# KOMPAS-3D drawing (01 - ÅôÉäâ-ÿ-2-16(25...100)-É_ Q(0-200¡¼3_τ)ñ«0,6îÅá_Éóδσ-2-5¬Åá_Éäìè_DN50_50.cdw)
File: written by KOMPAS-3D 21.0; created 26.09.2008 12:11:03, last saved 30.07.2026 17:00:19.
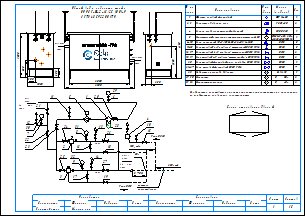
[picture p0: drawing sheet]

Sheets 1-2: A3, landscape

Document properties: Наименование: Макро:21; Автор: RaskoAdmin; Форматы листов документа: 2xA3; Полное имя файла: \\UR38nt01\Departments\КТО\КБ ПУРДГ\Заявки\Прайс-лист на типовые шкафы ГРПШ\ПУРДГ_стандарт_30_04_2026\ПУРДГ с РДНК\ПУРДГ-Ш-2-16(25...100)-Р_ Q(0-200нм3_ч)до0,6МПа_Рвых-2-5кПа_РДНК_DN50_50.cdw

Title block, sheet 1: Наименование: Пункт учета газа / ПУГ-Ш-400-Р / ЛГТИ.485922.001ТУ; designation: ЛГТИ.03.4411141; sheet number: 1; Количество листов документа: 2; organisation: ООО "ЭЛЬСТЕР Газэлектроника"; Форматы листов документа: A3; stored path: C:\Рабочие документы\Компас\ПУГ\Схема.cdw; Разработал: Устинов; Проверил: Кошкин; Утвердил: Кошкин
Title block, sheet 2: sheet number: 2; stored path: D:\Рабочие документы\Заявки\ПУРДГ\ПУРДГ-ШУЭО-2-100-Р 4411220.cdw; designation, second copy: ЛГТИ.03.4411141-

Views: Вид 1, Вид 2
Referenced files: wcvoit.frw
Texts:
  Normal
  № на
  схеме
  Усл.
  обозн.
  Марка
  (модель)
  Кол.
  Фильтр газовый фланцевый
  ФГ 16-50
  Регулятор давления газа
  РДНК-50
  Клапан предохранительный сбросной
  КПС DN20
  Измерительный комплекс с ротационным счетчиком Ду50
  СГ-ЭК-Р-(0,2...2,0)-
  Кран кнопочный VE-РАСКО-НЗ-1,6-G1/2-М20
  DN15
  Кран шаровой "под приварку" штуцерный DN20 PN16
  DN20
  Кран шаровой "под приварку" штуцерный DN15 PN16
  Кран шаровой "под приварку" штуцерный п/п DN15 PN16
  Кран шаровой фланцевый с мех. приводом DN50 PN16
  Кран шаровой фланцевый DN50 PN16
  DN50
  Индикатор перепада давления
  Манометр
  Манометр-напоромер
  Delta 15
  0...     МПа
  0...     кПа
  Общий вид и габариты шкафа
  ПУРДГ-Ш-2-16(25...100)-Р
  Выход газа
  Вход газа
  logo-rasko-ge.png
  DN 1
  местное
  сопротивление
  Римп DN15
  Римп DN20
  Выход
  газа
  Р=     кПа
  Вход
  Р=       МПа
  PDI
  Схема открывания дверей
  Предприятие изготовитель может заменять комплектующие на аналогичные,
  не ухудшающие заявленных характеристик.
  Должность
  Конструктор
  Фамилия
  Подпись
  Дата
  Согласовано
  Максимкин
  Лист
  Листов
  POLYLINE_STYLE_0.18_RGB_0_0_0
  POLYLINE_STYLE_0.50_RGB_0_0_0
  POLYLINE_STYLE_0.34_RGB_0_0_0
  PHANTOM_RGB_0_0_0_SC_1_THICK_0.18
  K5LT_THIN_RGB_0_0_0_THICK_0.18
  K5LT32769_RGB_0_0_0_THICK_0.18
  K5LT12_RGB_0_0_0_SC_1_THICK_0.18
  K5LT_DASHED_RGB_0_0_0_SC_1_THICK_0.18
  ACISOTGL_RGB_0_0_0_SC_0.8_THICK_0.25
  CONTINUOUS_RGB_0_127_31_THICK_0.3
  CONTINUOUS_RGB_0_0_255_THICK_0.35
  CONTINUOUS_RGB_255_0_0_THICK_0.35
  POLYLINE_STYLE_0.25_RGB_0_0_0
  CONTINUOUS_RGB_0_0_0_THICK_0.5
  POLYLINE_STYLE_0.35_RGB_0_0_255
  CONTINUOUS_RGB_0_0_0_THICK_0.4
  CONTINUOUS_RGB_0_0_0_THICK_0.35
  НЕВИДИМАЯ_RGB_0_0_0_SC_0.3_THICK_0.25
  СONTINUOUS_RGB_0_0_0_THICK_0.25
  ОСЕВАЯ2_RGB_248_153_30_SC_0.3_THICK_0.25
  Без оформления
Dimensions and other numbers on the sheet: 1; 2, 3; 2; 4; 5; 6-10; 11-15; 16, 17; 18, 19; 20; 21-27; 7; 28; 29, 30; 31, 32; 1500; 250; 300; 1050; 550; 305; 2000; 4130; 2300; 5,,,7DN 1; 30; 12; 21; 22; 23; 11; 6; 29; 24; 31; 8; 16; 13; 26; 18; 10; 15; 25; 32; 9; 3; 17; 14; 27; 19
